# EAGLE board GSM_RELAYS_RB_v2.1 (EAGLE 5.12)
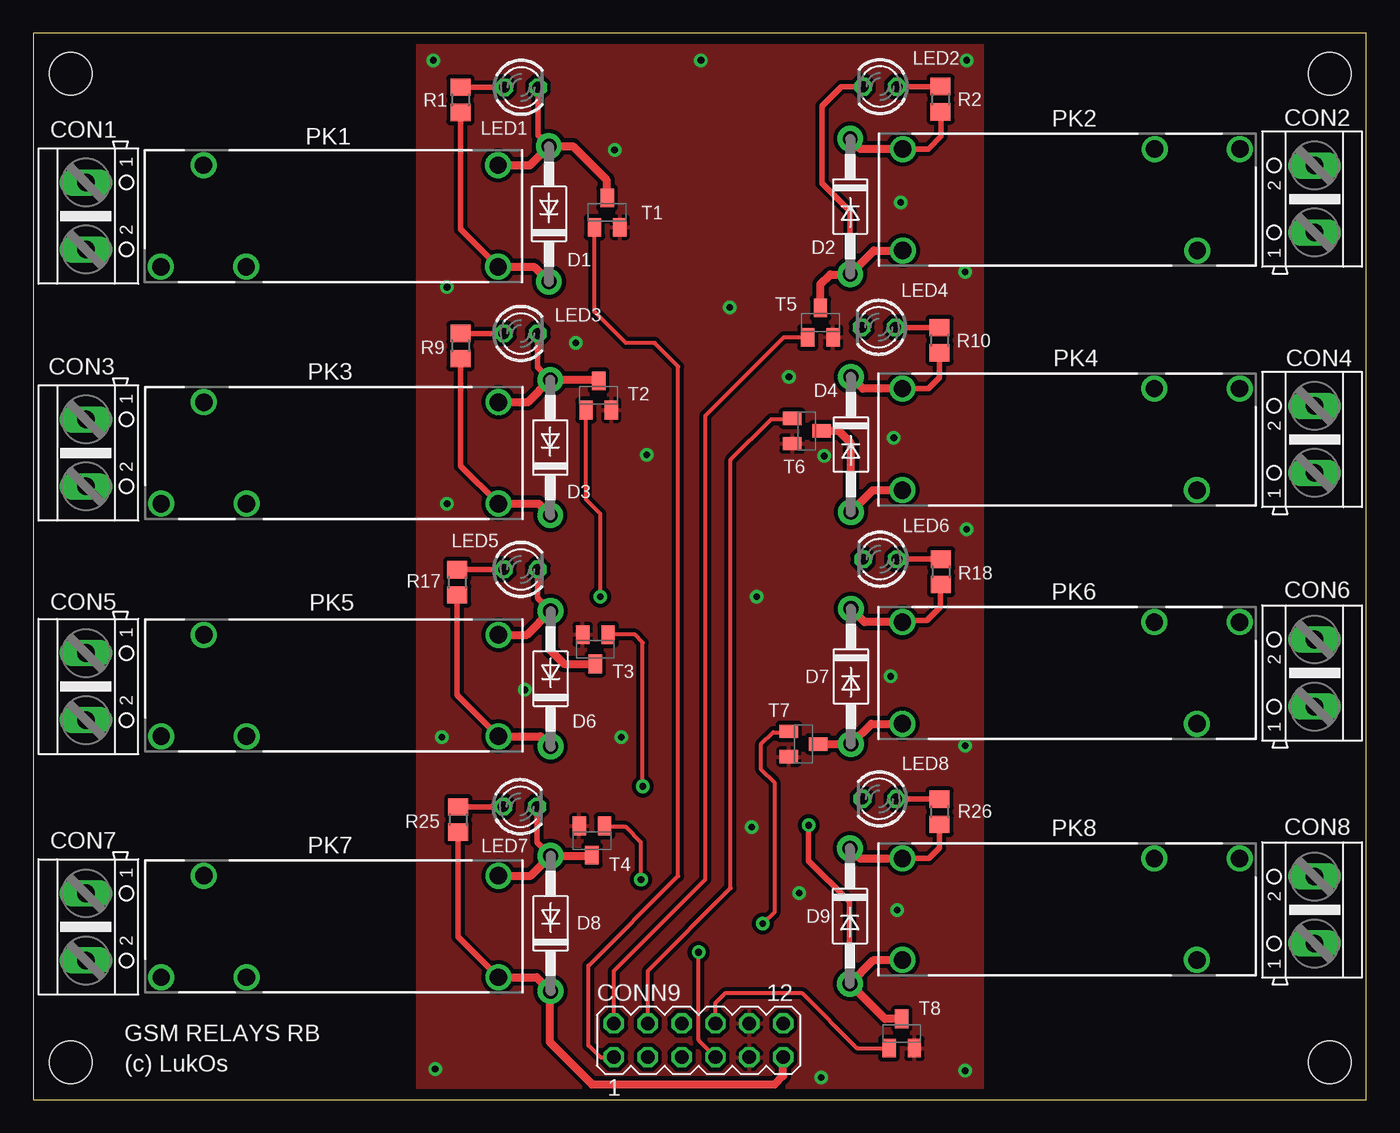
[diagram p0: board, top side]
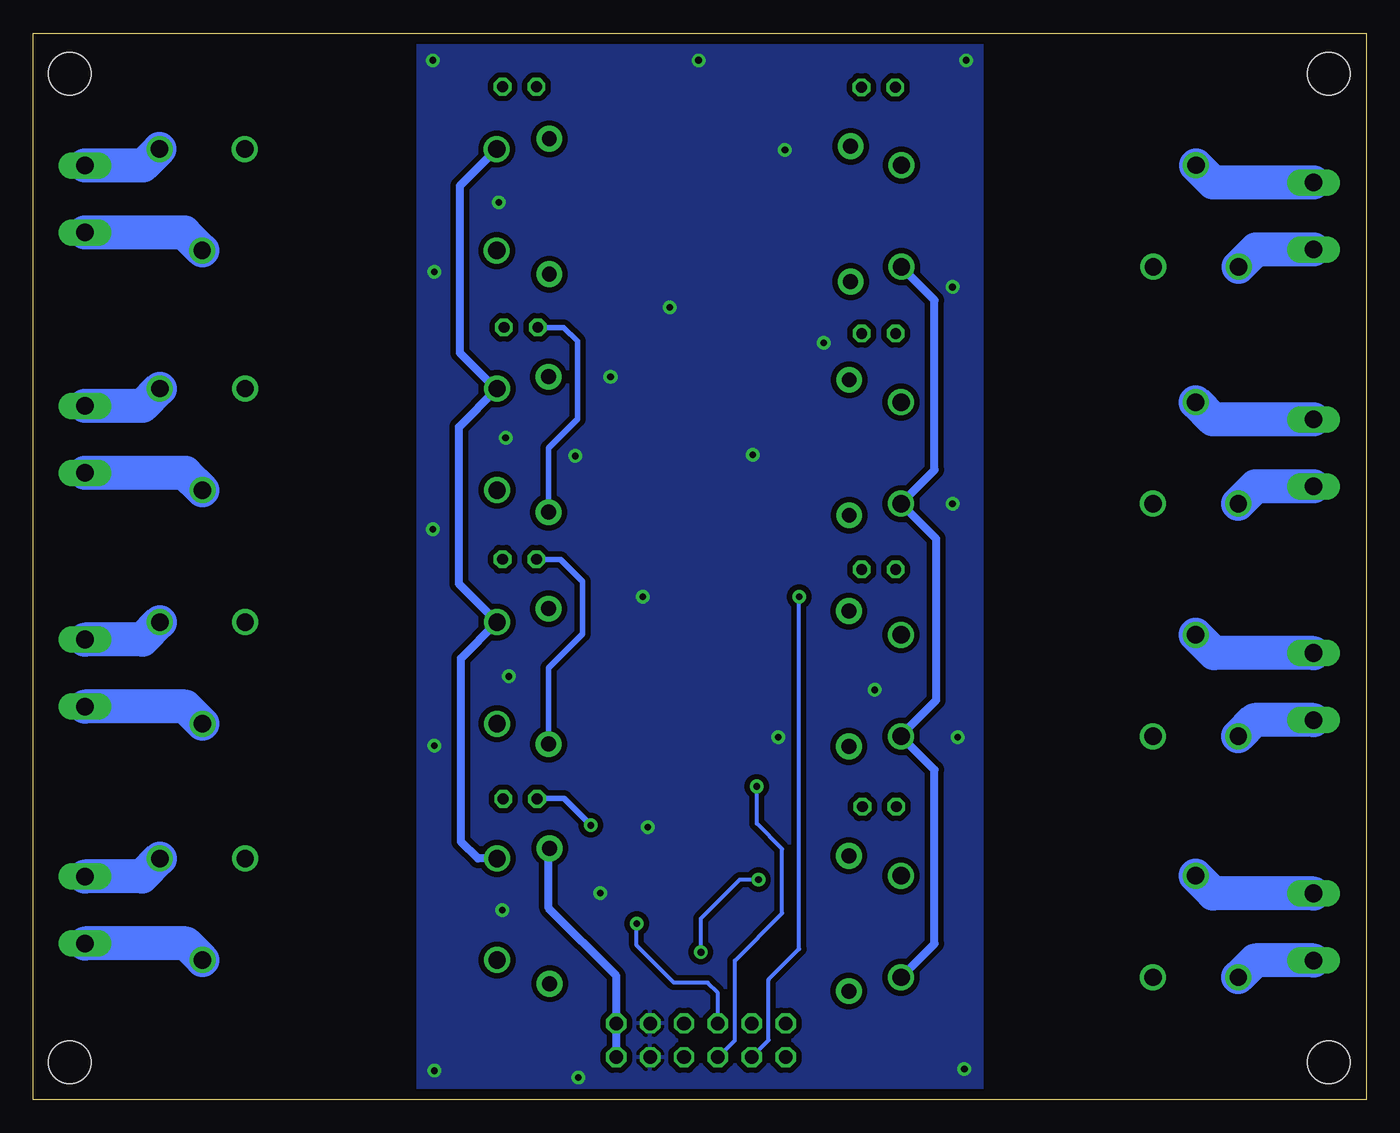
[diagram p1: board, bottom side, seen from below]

Size 100 x 80 mm. Coordinates in mm from the lower left corner, seen from the top.
Outline: 0,0 100,0 100,80 0,80 0,0
Copper layers (1*16): Top 0.035mm / dielectric 1.5mm / Bottom 0.035mm
Design rules "default *": minimum track width 10mil, minimum drill 19mil, track to track 8mil, track to pad 8mil, pad to pad 8mil, via to via 8mil, smd to smd 8mil, copper to edge 32mil, drill to drill 8mil, minimum pad ring 10mil, minimum via ring 8mil, stop-mask expansion 4mil, vias tented up to drill 0mil, thermal gap 10mil
Holes 3.2 mm at 2.79,76.96 2.79,2.79 97.28,2.79 97.28,76.96
tRestrict: area 65,4.3 to 65.5,4.4; area 41.9,33.9 to 42.4,34; area 42.2,52.5 to 42.7,52.6; area 42.8,66 to 43.3,66.2; area 58.8,57.8 to 59.3,57.9; area 57.8,49.8 to 57.9,50.3; area 41.7,19.7 to 42.2,19.8; area 57.4,26.4 to 57.5,26.9

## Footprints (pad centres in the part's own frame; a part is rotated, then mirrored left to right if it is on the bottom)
AK500/2 = drill 1.321 long: 1 -2.515,0; 2 2.515,0
MA06-2 = drill 1.016 octagon: 1 -6.35,-1.27; 2 -6.35,1.27; 3 -3.81,-1.27; 4 -3.81,1.27; 5 -1.27,-1.27; 6 -1.27,1.27; 7 1.27,-1.27; 8 1.27,1.27; 9 3.81,-1.27; 10 3.81,1.27; 11 6.35,-1.27; 12 6.35,1.27
DO41-10 = drill 1.118 pad 1.93 round: A 5.08,0; C -5.08,0
LED3MM = drill 0.813 octagon: A -1.27,0; K 1.27,0
RY-II = drill 1.3 round: 11 9.4,-3.81; 12 6.2,3.81; 14 12.6,3.81; A1 -12.7,-3.81; A2 -12.7,3.81
R0805 = smd 1.3 x 1.5: 1 -0.95,0; 2 0.95,0
SOT23-BEC = smd 1 x 1.4: B -0.95,-1.1; C 0,1.1; E 0.95,-1.1

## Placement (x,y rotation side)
CON1  [AK500/2]  3.94,66.29 270 top
CON2  [AK500/2]  96.14,67.56 90 top
CON3  [AK500/2]  3.94,48.51 270 top
CON4  [AK500/2]  96.14,49.53 90 top
CON5  [AK500/2]  3.94,30.99 270 top
CON6  [AK500/2]  96.14,32 90 top
CON7  [AK500/2]  3.94,12.95 270 top
CON8  [AK500/2]  96.14,14.22 90 top
CONN9  [MA06-2]  49.91,4.45 0 top
D1  1N4007  [DO41-10]  38.68,66.45 90 top
D2  1N4007  [DO41-10]  61.29,67.01 270 top
D3  1N4007  [DO41-10]  38.79,48.92 90 top
D4  1N4007  [DO41-10]  61.34,49.15 270 top
D6  1N4007  [DO41-10]  38.81,31.57 90 top
D7  1N4007  [DO41-10]  61.34,31.75 270 top
D8  1N4007  [DO41-10]  38.81,13.21 90 top
D9  1N4007  [DO41-10]  61.26,13.77 270 top
LED1  [LED3MM]  36.6,75.95 0 top
LED2  [LED3MM]  63.53,76 180 top
LED3  [LED3MM]  36.58,57.48 0 top
LED4  [LED3MM]  63.42,57.94 180 top
LED5  [LED3MM]  36.58,39.78 0 top
LED6  [LED3MM]  63.53,40.54 180 top
LED7  [LED3MM]  36.53,21.97 0 top
LED8  [LED3MM]  63.47,22.56 180 top
PK1  HF68F  [RY-II]  22.17,66.29 180 top
PK2  HF68F  [RY-II]  77.93,67.51 0 top
PK3  HF68F  [RY-II]  22.2,48.51 180 top
PK4  HF68F  [RY-II]  77.9,49.53 0 top
PK5  HF68F  [RY-II]  22.2,31.06 180 top
PK6  HF68F  [RY-II]  77.9,32 0 top
PK7  HF68F  [RY-II]  22.2,12.98 180 top
PK8  HF68F  [RY-II]  77.9,14.27 0 top
R1  2k  [R0805]  32.05,75.01 270 top
R2  2k  [R0805]  68.07,75.06 270 top
R9  2k  [R0805]  32.05,56.54 270 top
R10  2k  [R0805]  68,56.97 270 top
R17  2k  [R0805]  31.8,38.81 270 top
R18  2k  [R0805]  68.1,39.6 270 top
R25  2k  [R0805]  31.88,21.01 270 top
R26  2k  [R0805]  68,21.59 270 top
T1  BCR112  [SOT23-BEC]  43.05,66.55 0 top
T2  BCR112  [SOT23-BEC]  42.42,52.83 0 top
T3  BCR112  [SOT23-BEC]  42.16,33.78 180 top
T4  BCR112  [SOT23-BEC]  41.91,19.43 180 top
T5  BCR112  [SOT23-BEC]  59.05,58.29 0 top
T6  BCR112  [SOT23-BEC]  58.04,50.16 270 top
T7  BCR112  [SOT23-BEC]  57.78,26.67 270 top
T8  BCR112  [SOT23-BEC]  65.15,4.95 0 top

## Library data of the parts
CON1-CON8 = con-ptr500; OC_FARNELL: unknown; OC_NEWARK: unknown
CONN9 = con-lstb; OC_FARNELL: unknown; OC_NEWARK: unknown
D1-D4 D6-D9 = diode-1
LED1-LED8 = led
PK1-PK8 = relay; MF: TYCO ELECTRONICS; MPN: RY210005; OC_FARNELL: unknown; OC_NEWARK: 08H3762
R1 R2 R9 R10 R17 R18 R25 R26 = rcl
T1-T8 = digital-transistors

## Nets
+12V: CONN9.11 CONN9.12 D1.C D2.C D3.C D4.C D6.C D7.C D8.C D9.C PK1.A2 PK2.A2 PK3.A2 PK4.A2 PK5.A2 PK6.A2 PK7.A2 PK8.A2 R1.2 R2.2 R9.2 R10.2 R17.2 R18.2 R25.2 R26.2
AGND: CONN9.9 CONN9.10 T1.E T2.E T3.E T4.E T5.E T6.E T7.E T8.E
N$14: D1.A LED1.K PK1.A1 T1.C
N$15: LED1.A R1.1
N$16: D3.A LED3.K PK3.A1 T2.C
N$17: CON1.1 PK1.11
N$18: CON1.2 PK1.14
N$19: LED3.A R9.1
N$20: CON3.1 PK3.11
N$21: CON3.2 PK3.14
N$27: D6.A LED5.K PK5.A1 T3.C
N$28: LED5.A R17.1
N$29: CON5.1 PK5.11
N$30: CON5.2 PK5.14
N$36: D8.A LED7.K PK7.A1 T4.C
N$37: LED7.A R25.1
N$38: CON7.1 PK7.11
N$39: CON7.2 PK7.14
N$45: D2.A LED2.K PK2.A1 T5.C
N$46: LED2.A R2.1
N$47: CON2.1 PK2.11
N$48: CON2.2 PK2.14
N$54: D4.A LED4.K PK4.A1 T6.C
N$55: LED4.A R10.1
N$56: CON4.1 PK4.11
N$57: CON4.2 PK4.14
N$63: D7.A LED6.K PK6.A1 T7.C
N$64: LED6.A R18.1
N$65: CON6.1 PK6.11
N$66: CON6.2 PK6.14
N$72: D9.A LED8.K PK8.A1 T8.C
N$73: LED8.A R26.1
N$74: CON8.1 PK8.11
N$75: CON8.2 PK8.14
OUT1: CONN9.1 T1.B
OUT2: CONN9.2 T5.B
OUT3: CONN9.3 T2.B
OUT4: CONN9.4 T6.B
OUT5: CONN9.5 T3.B
OUT6: CONN9.6 T7.B
OUT7: CONN9.7 T4.B
OUT8: CONN9.8 T8.B

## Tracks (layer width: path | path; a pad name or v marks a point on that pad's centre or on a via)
+12V
  Top 0.406: R1.2 32.05,65.3 PK1.A2 | R9.2 32.05,47.55 PK3.A2 | R17.2 31.8,30.35 PK5.A2 | R25.2 31.88,12.19 PK7.A2 | PK2.A2 67.16,71.32 68.1,72.26 68.1,74.08 R2.2 | R18.2 68.07,38.62 68.07,36.96 67.06,35.94 65.33,35.94 PK6.A2 | R10.2 68,54.18 67.16,53.34 PK4.A2 | R26.2 68,18.9 67.18,18.09 PK8.A2
  Top 0.61: PK1.A2 37.57,62.48 D1.C | PK3.A2 37.92,44.7 D3.C | PK5.A2 38.05,27.25 D6.C | PK7.A2 37.77,9.17 D8.C 38.73,8.05 38.73,4.32 41.91,1.14 55.63,1.14 56.26,1.78 CONN9.11 | PK8.A2 62.03,18.09 D9.C | PK6.A2 62.36,35.81 D7.C | PK4.A2 62.23,53.34 D4.C | PK2.A2 62.05,71.32 D2.C
  Bottom 0.61: PK7.A2 32.38,11.68 32.38,24.74 PK5.A2 34.9,27.33 32.26,29.97 32.26,42.06 PK3.A2 | PK3.A2 34.87,44.7 | PK1.A2 34.87,62.46 32.38,59.97 32.38,47.24 34.9,44.73 PK3.A2 | PK8.A2 66.65,18.09 67.91,19.34 67.91,33.11 PK6.A2 68.07,38.68 68.07,50.47 PK4.A2 65.31,53.34 R10.2 68,68.56 PK2.A2 | D9.C 61.34,18.77 61.34,14.35 56.26,9.27 CONN9.12 CONN9.11
AGND  (via drill 0.5 pad 1.02)
  other vias: 59.33,48.29 30.15,2.29 69.9,2.16 30.02,77.98 70.03,77.98 31.04,60.96 31.04,44.7 64.57,49.66 65.07,67.31 64.31,31.75 64.82,14.22 36.88,30.73 40.69,56.77 43.61,71.25 52.25,59.44 56.69,54.23 46.02,48.39 30.66,27.18 69.9,62.1 70.03,42.8 69.9,26.54 50.09,77.98 54.28,37.72 44.12,27.18 53.9,20.45 59.11,1.65 57.45,15.49
  pour Bottom (isolate 0.406): 28.83,79.88 71.12,79.88 71.12,0.13 28.83,0.13
  pour Top (isolate 0.305): 28.91,79.88 71.17,79.88 71.17,0.18 28.88,0.18 28.88,79.83
N$14
  Top 0.406: LED1.K 37.87,72.34 D1.A
  Top 0.61: PK1.A1 37.26,70.1 D1.A 40.49,71.53 43,69.01 43,67.7 T1.C
N$15
  Top 0.406: LED1.A 32.06,75.95 R1.1
N$16
  Top 0.406: LED3.K 37.85,54.94 D3.A
  Top 0.61: PK3.A1 37.11,52.32 D3.A 42.35,54 T2.C
N$17
  Bottom 2.54: CON1.1 11.48,68.81 PK1.11
N$18
  Bottom 2.54: CON1.2 8.28,63.78 PK1.14
N$19
  Top 0.406: LED3.A 32.06,57.48 R9.1
N$20
  Bottom 2.54: CON3.1 11.5,51.03 PK3.11
N$21
  Bottom 2.54: CON3.2 8.3,46 PK3.14
N$27
  Top 0.406: LED5.K 37.85,37.62 D6.A
  Top 0.61: PK5.A1 37.03,34.87 D6.A 38.76,36.6 38.76,33.73 39.81,32.68 T3.C
N$28
  Top 0.406: R17.1 35.29,39.76 LED5.A
N$29
  Bottom 2.54: CON5.1 11.43,33.5 PK5.11
N$30
  Bottom 2.54: CON5.2 8.38,28.47 PK5.14
N$36
  Top 0.305: T4.C 41.91,18.3 41.92,18.29
  Top 0.406: LED7.K 37.8,19.3 D8.A
  Top 0.61: PK7.A1 37.31,16.79 D8.A 41.92,18.29
N$37
  Top 0.406: LED7.A 31.89,21.97 R25.1
N$38
  Bottom 2.54: CON7.1 11.48,15.47 PK7.11
N$39
  Bottom 2.54: CON7.2 8.33,10.44 PK7.14
N$45
  Top 0.406: LED2.K 60.63,76 59.16,74.52 59.16,68.76 61.27,66.65 61.27,61.95 D2.A
  Top 0.61: PK2.A1 63.07,63.7 D2.A 61.27,61.9 59.79,61.9 59.05,61.16 T5.C
N$46
  Top 0.406: LED2.A 68.06,76 R2.1
N$47
  Bottom 2.54: CON2.1 88.67,65.05 PK2.11
N$48
  Bottom 2.54: CON2.2 91.77,70.08 PK2.14
N$54
  Top 0.61: PK4.A1 62.99,45.72 D4.A | D4.A 61.27,44.15 | D4.A 61.34,49.25 60.43,50.16 T6.C
  Bottom 0.406: LED4.K 60.22,57.94 59.18,56.9 59.18,51.05 61.34,48.9 D4.A
N$55
  Top 0.406: LED4.A 67.98,57.94 R10.1
N$56
  Bottom 2.54: CON4.1 88.6,47.02 PK4.11
N$57
  Bottom 2.54: CON4.2 91.8,52.05 PK4.14
N$63
  Top 0.61: PK6.A1 62.87,28.19 D7.A T7.C
  Bottom 0.406: 62.28,40.54 LED6.K 62.23,40.51 60.45,40.51 58.8,38.86 58.8,34.92 61.34,32.38 D7.A
N$64
  Top 0.406: LED6.A 68.09,40.54 R18.1
N$65
  Bottom 2.54: CON6.1 88.6,29.49 PK6.11
N$66
  Bottom 2.54: CON6.2 91.8,34.52 PK6.14
N$72  (via drill 0.5 pad 1.02)
  Top 0.406: v58.17,20.57 58.17,17.91 61.21,14.86 61.21,8.74 D9.A
  Top 0.61: PK8.A1 63.04,10.46 D9.A 63.9,6.05 T8.C
  Bottom 0.406: LED8.K 62.15,22.61 60.2,22.61 v58.17,20.57
N$73
  Top 0.406: LED8.A 67.98,22.55 R26.1
N$74
  Bottom 2.54: CON8.1 88.55,11.71 PK8.11
N$75
  Bottom 2.54: CON8.2 91.85,16.74 PK8.14
OUT1
  Top 0.305: T1.B 42.1,59.12 44.45,56.77 46.61,56.77 48.39,54.99 48.39,16.76 41.66,10.03 41.66,4.06 42.55,3.17 CONN9.1
OUT2
  Top 0.305: T5.B 56.3,57.19 50.42,51.31 50.42,16.51 43.56,9.65 CONN9.2
OUT3  (via drill 0.5 pad 1.02)
  Top 0.305: v42.55,37.72 42.55,43.94 41.47,45.02 T2.B
  Bottom 0.305: v42.55,37.72 42.55,11.3 44.83,9.02 44.83,4.45 CONN9.3
OUT4
  Top 0.305: CONN9.4 46.1,9.65 52.32,15.88 52.32,48.01 55.37,51.05 56.88,51.05 T6.B
OUT5  (via drill 0.5 pad 1.02)
  Top 0.305: T3.B 45.13,34.88 45.72,34.29 v45.72,23.5
  Bottom 0.305: CONN9.5 47.37,4.45 47.37,10.41 43.81,13.97 43.81,18.8 45.72,20.7 v45.72,23.5
OUT6  (via drill 0.5 pad 1.02)
  Top 0.305: v54.74,13.21 55.63,14.1 55.63,23.75 54.61,24.77 54.61,26.67 55.5,27.56 56.62,27.56 T7.B
  Bottom 0.305: v54.74,13.21 54.74,11.56 51.94,8.76 49.4,8.76 48.64,8 CONN9.6
OUT7  (via drill 0.5 pad 1.02)
  Top 0.305: CONN9.7 49.91,4.45 v49.91,11.05 | v45.59,16.51 45.59,19.3 44.45,20.45 42.94,20.45 T4.B
  Bottom 0.305: v49.91,11.05 49.91,13.59 46.99,16.51 v45.59,16.51
OUT8
  Top 0.305: CONN9.8 51.18,7.24 51.94,8 57.66,8 61.81,3.85 T8.B

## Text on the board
tNames: GSM RELAYS RB | (c) LukOs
